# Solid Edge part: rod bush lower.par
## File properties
Author: Robert a Rhodes jr
Template: Normal.par
Last saved by: CADCIM
Revision: 6
Application: Solid Edge
Accuracy: 0.99
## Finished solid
Body 1: solid body, 4 faces, 4 edges, 0 vertices.
  Faces by surface: cylinder 2, plane 2
  Edges by curve: circle 4
Bounding box of the edges (mm): 15.000 x 15.000 x 24.000, from (-7.5, -7.5, -24) to (7.5, 7.5, 0).
Cylindrical faces by radius (mm): R6 x1, R7.5 x1
Planar faces by outward normal: +z 1, -z 1
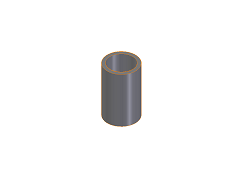
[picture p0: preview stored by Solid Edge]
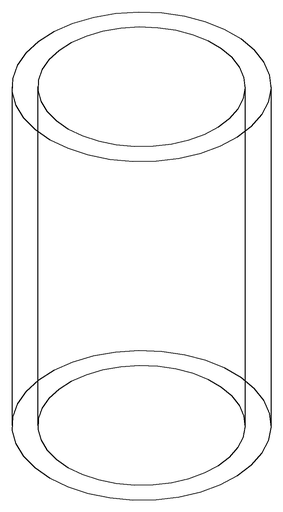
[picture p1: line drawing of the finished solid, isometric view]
